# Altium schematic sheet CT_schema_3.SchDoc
size 461 x 327 mm
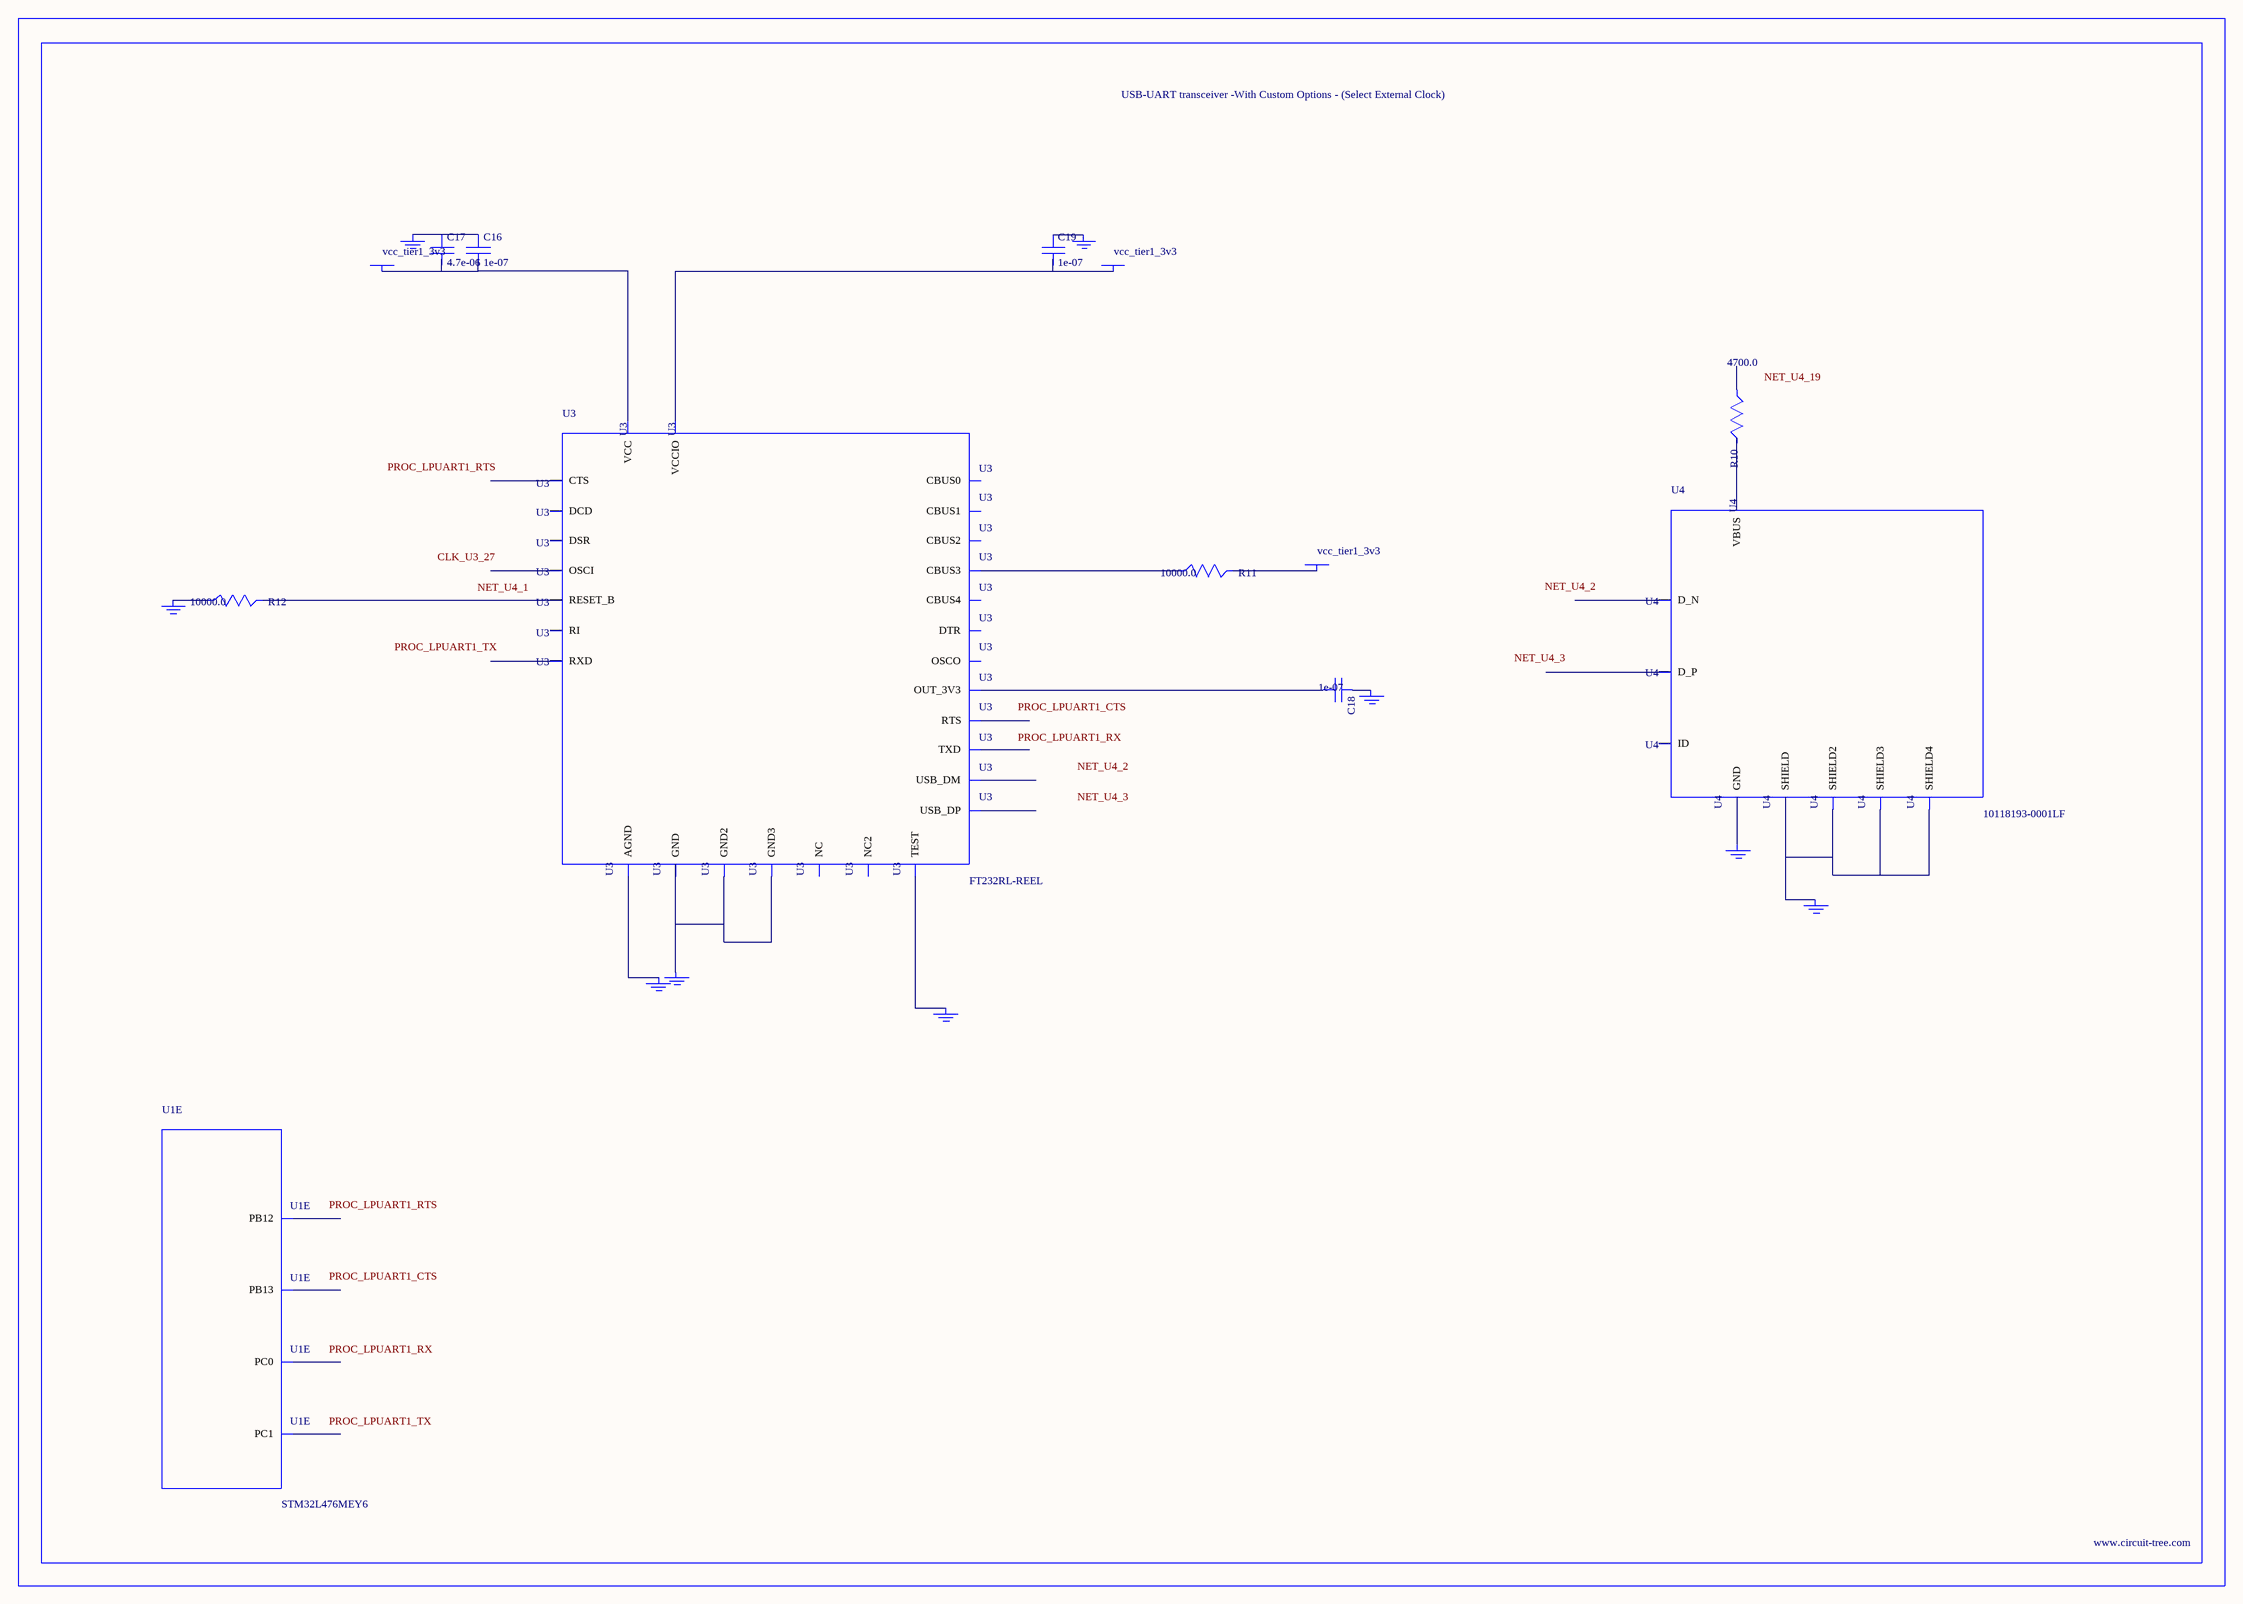
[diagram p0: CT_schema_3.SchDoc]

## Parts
BORDER2  (no value)
C16  1e-07  [C0402]
C17  4.7e-06  [C0805]
C18  1e-07  [C0402]
C19  1e-07  [C0402]
GND_INSTANCE_2_0  (no value)
GND_INSTANCE_2_1  (no value)
GND_INSTANCE_2_2  (no value)
GND_INSTANCE_2_3  (no value)
GND_INSTANCE_2_4  (no value)
GND_INSTANCE_2_5  (no value)
GND_INSTANCE_2_6  (no value)
GND_INSTANCE_2_7  (no value)
GND_INSTANCE_2_8  (no value)
POWER_INSTANCE_2_0  vcc_tier1_3v3
POWER_INSTANCE_2_1  vcc_tier1_3v3
POWER_INSTANCE_2_2  vcc_tier1_3v3
R10  4700.0  [R0603]
R11  10000.0  [R0603]
R12  10000.0  [R0603]
U1  STM32L476MEY6  [WLCSP81]  (part E of 9)
U3  FT232RL-REEL  [SSOP-28]
U4  10118193-0001LF  [FCI_10118193-0001LF]

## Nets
NetC16_1: C16.1 C17.1 GND_INSTANCE_2_3.0(GND)
NetC16_2: C16.2 C17.2 POWER_INSTANCE_2_2.0(PWR) U3.20(VCC)
NetC18_1: C18.1 GND_INSTANCE_2_1.0(GND)
NetC18_2: C18.2 U3.17(OUT_3V3)
NetC19_1: C19.1 GND_INSTANCE_2_0.0(GND)
NetC19_2: C19.2 POWER_INSTANCE_2_0.0(PWR) U3.4(VCCIO)
NetGND_INSTANCE_2_2_0: GND_INSTANCE_2_2.0(GND) R12.1
NetGND_INSTANCE_2_4_0: GND_INSTANCE_2_4.0(GND) U3.25(AGND)
NetGND_INSTANCE_2_5_0: GND_INSTANCE_2_5.0(GND) U3.26(TEST)
NetGND_INSTANCE_2_6_0: GND_INSTANCE_2_6.0(GND) U3.7(GND) U3.18(GND2) U3.21(GND3)
NetGND_INSTANCE_2_7_0: GND_INSTANCE_2_7.0(GND) U4.6(SHIELD) U4.7(SHIELD2) U4.8(SHIELD3) U4.9(SHIELD4)
NetGND_INSTANCE_2_8_0: GND_INSTANCE_2_8.0(GND) U4.5(GND)
NetPOWER_INSTANCE_2_1_0: POWER_INSTANCE_2_1.0(PWR) R11.2
NetR10_2: R10.2 U4.1(VBUS)
NetR11_1: R11.1 U3.14(CBUS3)
NetR12_2: R12.2 U3.19(RESET_B)

Not connected (* = marked no-connect by the designer): R10 1; U1 F8(PC1) F9(PC0) H1(PB12) H2(PB13); U3 1(TXD) 2(DTR) 3(RTS) 5(RXD) 6(RI) 8(NC) 9(DSR) 10(DCD) 11(CTS) 12(CBUS4) 13(CBUS2) 15(USB_DP) 16(USB_DM) 22(CBUS1) 23(CBUS0) 24(NC2) 27(OSCI) 28(OSCO); U4 2(D_N) 3(D_P) 4(ID)

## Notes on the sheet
- Labels drawn without touching a wire or pin: CLK_U3_27, NET_U4_1, NET_U4_2, NET_U4_3, NET_U4_19, PROC_LPUART1_CTS, PROC_LPUART1_RTS, PROC_LPUART1_RX, PROC_LPUART1_TX

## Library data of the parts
BORDER2 = BORDER_PAGE2
C16 C18 C19 = C0402C104K3RACTU
C17 = C0805C475K4RACTU
GND_INSTANCE_2_0-GND_INSTANCE_2_8 = GND
POWER_INSTANCE_2_0-POWER_INSTANCE_2_2 = PWR
R10 = RC0603JR-074K7L
R11 R12 = RC0603JR-0710KL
